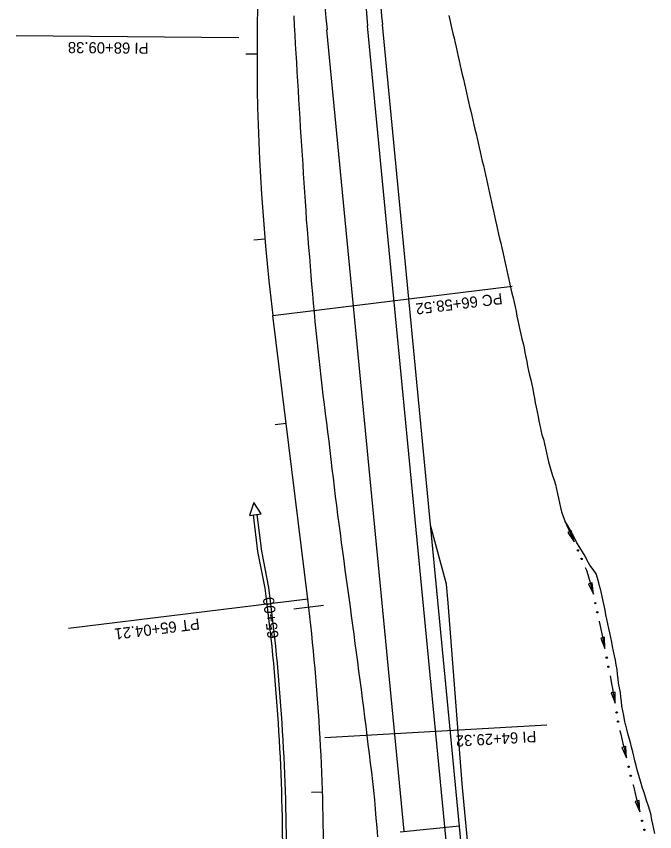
# Model space of a CAD drawing. Extents: x 1304554 to 1314558, y 2088110 to 2090513.
# Drawn here: x 1313834.3 to 1314178.7, y 2089497.1 to 2089937.1 of the extents above; entities that cross this region are included whole.
import ezdxf

# ---------------------------------------------------------------- set-up
doc = ezdxf.new("R2010")
doc.units = 0
for name, color, linetype in [('MOT_Barrier Wall Stage 3', 7, 'Continuous'), ('MOT_TIAB_Stage 3', 7, 'Continuous'), ('R_Horz Alg', 7, 'Continuous'), ('R_Horz Alg Annot', 7, 'Continuous'), ('R_Horz Alg Stationing', 7, 'Continuous'), ('R_Proposed Const Limits', 7, 'Continuous'), ('R_Proposed Road', 7, 'Continuous'), ('R_Shld_GR', 7, 'Continuous'), ('R_Shoulder', 7, 'Continuous'), ('R_Special Ditch', 7, 'Continuous')]:
    doc.layers.add(name, color=color, linetype=linetype)

msp = doc.modelspace()

# ---------------------------------------------------------------- linework, layer by layer
at = {"layer": 'MOT_Barrier Wall Stage 3'}
for p, q in [((1313962.26, 2089668.05), (1313964.24, 2089668.3)), ((1313964.69, 2089648.2), (1313962.26, 2089668.05)), ((1313966.68, 2089648.45), (1313964.24, 2089668.3)), ((1313968.62, 2089628.54), (1313964.69, 2089648.2)), ((1313970.6, 2089628.78), (1313966.68, 2089648.45)), ((1313969.69, 2089619.81), (1313968.62, 2089628.54)), ((1313971.68, 2089620.05), (1313970.6, 2089628.78))]:
    msp.add_line(p, q, dxfattribs=at)
for radius in [1123.92, 1125.92]:
    msp.add_arc((1312854.15, 2089482.84), radius, 359.5, 7, dxfattribs=at)
at = {"layer": 'MOT_TIAB_Stage 3'}
msp.add_lwpolyline([(1313962.43, 2089674.8), (1313960.13, 2089667.79), (1313966.36, 2089668.56)], close=True, dxfattribs=at)
at = {"layer": 'R_Horz Alg'}
msp.add_line((1313991.53, 2089622.49), (1313972.72, 2089775.65), dxfattribs=at)
msp.add_line((1313991.53, 2089622.49), (1313972.72, 2089775.65), dxfattribs=at)
for centre, start, end in [((1315110.09, 2089915.3), 172, 187), ((1312854.15, 2089482.84), 359.5, 7), ((1312854.15, 2089482.84), 359.5, 7)]:
    msp.add_arc(centre, 1145.92, start, end, dxfattribs=at)
at = {"layer": 'R_Horz Alg Annot'}
for points in [[(1313954.34, 2089925.39), (1313834.34, 2089926.44)], [(1313972.72, 2089775.65), (1314101.75, 2089791.49)], [(1313991.53, 2089622.49), (1313862.5, 2089606.65)], [(1314000.68, 2089547.94), (1314120.49, 2089554.75)]]:
    msp.add_lwpolyline(points, dxfattribs=at)
at = {"layer": 'R_Horz Alg Stationing'}
for points in [[(1313958.18, 2089916.79), (1313964.18, 2089916.78)], [(1313962.43, 2089816.39), (1313968.41, 2089816.91)], [(1313973.9, 2089716.84), (1313979.85, 2089717.57)], [(1313984.09, 2089617.37), (1313999.98, 2089619.26)], [(1313993.51, 2089518.44), (1313999.51, 2089518.62)]]:
    msp.add_lwpolyline(points, dxfattribs=at)
at = {"layer": 'R_Proposed Const Limits'}
for points in [[(1314029.32, 2089494.34), (1314028.9, 2089499.33), (1314028.49, 2089504.31), (1314028.08, 2089509.29), (1314027.64, 2089514.28), (1314027.18, 2089519.25), (1314026.65, 2089524.23), (1314026.02, 2089529.19), (1314025.4, 2089534.15), (1314024.79, 2089539.12), (1314024.17, 2089544.08), (1314023.57, 2089549.04), (1314022.97, 2089554.01), (1314022.37, 2089558.98), (1314021.76, 2089563.94), (1314021.13, 2089568.9), (1314020.46, 2089573.86), (1314019.79, 2089578.82), (1314019.13, 2089583.78), (1314018.47, 2089588.74), (1314017.81, 2089593.7), (1314017.16, 2089598.66), (1314016.51, 2089603.62), (1314015.85, 2089608.58), (1314015.17, 2089613.54), (1314014.5, 2089618.5), (1314013.83, 2089623.45), (1314013.16, 2089628.41), (1314012.48, 2089633.37), (1314011.79, 2089638.33), (1314011.11, 2089643.28), (1314010.44, 2089648.24), (1314009.78, 2089653.2), (1314009.12, 2089658.16), (1314008.48, 2089663.12), (1314007.84, 2089668.09), (1314007.2, 2089673.05), (1314006.57, 2089678.01), (1314005.94, 2089682.97), (1314005.33, 2089687.94), (1314004.74, 2089692.9), (1314004.18, 2089697.87), (1314003.62, 2089702.84), (1314003.02, 2089707.81), (1314002.42, 2089712.77), (1314001.8, 2089717.73), (1314001.15, 2089722.7), (1314000.5, 2089727.66), (1313999.86, 2089732.62), (1313999.26, 2089737.58), (1313998.73, 2089742.55), (1313998.2, 2089747.53), (1313997.67, 2089752.5), (1313997.14, 2089757.47), (1313996.62, 2089762.44), (1313996.11, 2089767.42), (1313995.6, 2089772.39), (1313995.08, 2089777.37), (1313994.61, 2089782.34), (1313994.2, 2089787.33), (1313993.79, 2089792.31), (1313993.38, 2089797.29), (1313992.97, 2089802.28), (1313992.57, 2089807.26), (1313992.16, 2089812.25), (1313991.75, 2089817.23), (1313991.33, 2089822.21), (1313990.94, 2089827.2), (1313990.62, 2089832.19), (1313990.29, 2089837.18), (1313989.97, 2089842.17), (1313989.64, 2089847.17), (1313989.3, 2089852.16), (1313988.97, 2089857.15), (1313988.65, 2089862.14), (1313988.3, 2089867.13), (1313987.94, 2089872.12), (1313987.65, 2089877.11), (1313987.38, 2089882.11), (1313987.1, 2089887.11), (1313986.79, 2089892.1), (1313986.49, 2089897.09), (1313986.2, 2089902.09), (1313985.9, 2089907.08), (1313985.58, 2089912.07), (1313985.25, 2089917.07), (1313984.93, 2089922.06), (1313984.67, 2089927.06), (1313984.41, 2089932.13), (1313984.15, 2089937.22)], [(1314067.61, 2089937.5), (1314068.16, 2089935.1), (1314068.72, 2089932.64), (1314069.28, 2089930.18), (1314069.84, 2089927.72), (1314070.41, 2089925.27), (1314070.97, 2089922.81), (1314071.51, 2089920.35), (1314072.05, 2089917.89), (1314072.61, 2089915.43), (1314073.18, 2089912.98), (1314073.75, 2089910.52), (1314074.32, 2089908.06), (1314074.89, 2089905.61), (1314075.47, 2089903.15), (1314076.03, 2089900.69), (1314076.58, 2089898.23), (1314077.13, 2089895.78), (1314077.7, 2089893.32), (1314078.27, 2089890.86), (1314078.85, 2089888.41), (1314079.43, 2089885.95), (1314080.02, 2089883.49), (1314080.59, 2089881.04), (1314081.16, 2089878.58), (1314081.73, 2089876.12), (1314082.29, 2089873.67), (1314082.86, 2089871.21), (1314083.42, 2089868.75), (1314083.98, 2089866.3), (1314084.54, 2089863.84), (1314085.1, 2089861.38), (1314085.67, 2089858.92), (1314086.24, 2089856.47), (1314086.8, 2089854.01), (1314087.35, 2089851.55), (1314087.9, 2089849.09), (1314088.45, 2089846.63), (1314088.99, 2089844.17), (1314089.53, 2089841.71), (1314090.07, 2089839.26), (1314090.63, 2089836.8), (1314091.19, 2089834.34), (1314091.74, 2089831.88), (1314092.3, 2089829.42), (1314092.85, 2089826.96), (1314093.39, 2089824.5), (1314093.93, 2089822.05), (1314094.47, 2089819.59), (1314095.03, 2089817.13), (1314095.59, 2089814.67), (1314096.15, 2089812.21), (1314096.71, 2089809.76), (1314097.27, 2089807.3), (1314097.83, 2089804.84), (1314098.39, 2089802.38), (1314098.95, 2089799.92), (1314099.5, 2089797.47), (1314100.04, 2089795.01), (1314100.58, 2089792.55), (1314101.13, 2089790.09), (1314101.69, 2089787.63), (1314102.25, 2089785.17), (1314102.26, 2089785.11), (1314102.81, 2089782.72), (1314103.37, 2089780.26), (1314103.89, 2089777.8), (1314104.37, 2089775.33), (1314104.85, 2089772.87), (1314105.38, 2089770.41), (1314105.95, 2089767.95), (1314106.52, 2089765.49), (1314107.08, 2089763.03), (1314107.65, 2089760.58), (1314108.21, 2089758.12), (1314108.7, 2089755.66), (1314109.16, 2089753.19), (1314109.63, 2089750.72), (1314110.13, 2089748.26), (1314110.67, 2089745.8), (1314111.22, 2089743.34), (1314111.77, 2089740.88), (1314112.31, 2089738.42), (1314112.85, 2089735.96), (1314113.3, 2089733.49), (1314113.75, 2089731.03), (1314114.19, 2089728.56), (1314114.67, 2089726.09), (1314115.2, 2089723.63), (1314115.72, 2089721.17), (1314116.25, 2089718.71), (1314116.77, 2089716.25), (1314117.08, 2089714.78), (1314117.27, 2089713.78), (1314117.7, 2089711.31), (1314118.65, 2089708.94), (1314118.66, 2089708.89), (1314119.17, 2089706.43), (1314119.7, 2089703.97), (1314120.29, 2089701.52), (1314120.87, 2089699.06), (1314121.46, 2089696.61), (1314122.04, 2089694.15), (1314122.74, 2089691.71), (1314123.54, 2089689.27), (1314124.35, 2089686.84), (1314125.08, 2089684.4), (1314125.62, 2089681.94), (1314126.16, 2089679.48), (1314126.7, 2089677.02), (1314127.26, 2089674.56), (1314127.86, 2089672.11), (1314128.46, 2089669.65), (1314129.34, 2089667.23)], [(1314178.65, 2089496.17), (1314178.16, 2089498.63), (1314177.67, 2089501.09), (1314177.17, 2089503.56), (1314176.76, 2089505.59), (1314176.68, 2089506.02), (1314176.04, 2089508.47), (1314175.27, 2089510.91), (1314174.49, 2089513.35), (1314173.72, 2089515.78), (1314172.94, 2089518.22), (1314172.16, 2089520.66), (1314171.39, 2089523.09), (1314170.64, 2089525.53), (1314169.89, 2089527.97), (1314169.19, 2089530.42), (1314168.59, 2089532.87), (1314167.99, 2089535.32), (1314167.39, 2089537.78), (1314166.79, 2089540.23), (1314166.18, 2089542.68), (1314165.58, 2089545.14), (1314164.91, 2089547.58), (1314164.24, 2089550.03), (1314163.56, 2089552.48), (1314163.01, 2089554.49), (1314162.92, 2089554.93), (1314162.44, 2089557.39), (1314161.94, 2089559.86), (1314161.44, 2089562.32), (1314160.96, 2089564.79), (1314160.7, 2089567.27), (1314160.43, 2089569.76), (1314160.16, 2089572.24), (1314159.68, 2089574.71), (1314159.2, 2089577.17), (1314158.89, 2089579.66), (1314158.61, 2089582.14), (1314158.33, 2089584.63), (1314157.95, 2089587.1), (1314157.47, 2089589.57), (1314156.99, 2089592.03), (1314156.5, 2089594.49), (1314155.98, 2089596.96), (1314155.47, 2089599.42), (1314154.97, 2089601.88), (1314154.46, 2089604.35), (1314153.96, 2089606.81), (1314153.43, 2089609.27), (1314152.9, 2089611.73), (1314152.38, 2089614.19), (1314151.86, 2089616.65), (1314151.33, 2089619.11), (1314150.8, 2089621.57), (1314150.25, 2089624.03), (1314149.72, 2089626.49), (1314149.35, 2089628.18), (1314149.27, 2089628.52), (1314149.15, 2089628.95), (1314148.48, 2089631.4), (1314147.8, 2089633.84), (1314147.03, 2089636.28), (1314145.49, 2089638.64), (1314143.71, 2089640.98), (1314142.26, 2089643.36), (1314141.1, 2089645.76), (1314139.74, 2089648.14), (1314138.22, 2089650.5), (1314136.75, 2089652.87), (1314135.56, 2089655.27), (1314134.37, 2089657.67), (1314133.03, 2089660.05), (1314131.6, 2089662.42), (1314130.27, 2089664.81)]]:
    msp.add_lwpolyline(points, dxfattribs=at)
at = {"layer": 'R_Proposed Road'}
for p, q in [((1314067.51, 2089477.98), (1314023.81, 2089931.84)), ((1314043.55, 2089497.3), (1314001.91, 2089929.73)), ((1314041.43, 2089497.1), (1314073.41, 2089500.18))]:
    msp.add_line(p, q, dxfattribs=at)
for radius, start in [(1420.39, 179.5), (1442.39, 181.3402)]:
    msp.add_arc((1315437.67, 2090067.97), radius, start, 185.5, dxfattribs=at)
at = {"layer": 'R_Shld_GR'}
for p, q in [((1314067.27, 2089620.62), (1314066.31, 2089630.58)), ((1314074.94, 2089520.83), (1314067.27, 2089620.62)), ((1314078.96, 2089479.08), (1314074.93, 2089520.9))]:
    msp.add_line(p, q, dxfattribs=at)
msp.add_lwpolyline([(1314066.31, 2089630.58), (1314057.79, 2089662.47)], dxfattribs=at)
at = {"layer": 'R_Shoulder'}
msp.add_line((1314075.48, 2089478.75), (1314031.77, 2089932.6), dxfattribs=at)
msp.add_arc((1315437.67, 2090067.97), 1412.39, 179.5, 185.5, dxfattribs=at)
at = {"layer": 'R_Special Ditch'}
for p, q in [((1314133.79, 2089659.35), (1314131.84, 2089658.5)), ((1314135.2, 2089653.42), (1314133.79, 2089659.35)), ((1314131.84, 2089658.5), (1314135.2, 2089653.42)), ((1314145.01, 2089631.39), (1314142.98, 2089630.79)), ((1314142.98, 2089630.79), (1314145.69, 2089625.33)), ((1314145.69, 2089625.33), (1314145.01, 2089631.39)), ((1314151.6, 2089601.99), (1314149.52, 2089601.57)), ((1314149.52, 2089601.57), (1314151.75, 2089595.9)), ((1314151.75, 2089595.9), (1314151.6, 2089601.99)), ((1314157.28, 2089572.47), (1314155.2, 2089572.11)), ((1314155.2, 2089572.11), (1314157.27, 2089566.38)), ((1314157.27, 2089566.38), (1314157.28, 2089572.47)), ((1314163.03, 2089543.07), (1314160.98, 2089542.58)), ((1314160.98, 2089542.58), (1314163.39, 2089536.99)), ((1314163.39, 2089536.99), (1314163.03, 2089543.07)), ((1314170.2, 2089513.91), (1314168.14, 2089513.4)), ((1314170.63, 2089507.84), (1314170.2, 2089513.91)), ((1314168.14, 2089513.4), (1314170.63, 2089507.84))]:
    msp.add_line(p, q, dxfattribs=at)
for points in [[(1314129.34, 2089667.23), (1314130.27, 2089664.81), (1314131.32, 2089662.39), (1314132.36, 2089659.98), (1314133.4, 2089657.57), (1314134.45, 2089655.16), (1314135.2, 2089653.42)], [(1314141.2, 2089639.67), (1314141.21, 2089639.64)], [(1314141.21, 2089639.64), (1314141.8, 2089638.29), (1314142.58, 2089635.85), (1314143.31, 2089633.41), (1314144.03, 2089630.97), (1314144.75, 2089628.53), (1314144.88, 2089628.1), (1314144.96, 2089627.76), (1314145.33, 2089626.07), (1314145.51, 2089625.28)], [(1314148.7, 2089610.63), (1314148.71, 2089610.59)], [(1314148.71, 2089610.59), (1314149.08, 2089608.85), (1314149.6, 2089606.39), (1314150.11, 2089603.93), (1314150.62, 2089601.46), (1314151.12, 2089599), (1314151.62, 2089596.54), (1314151.75, 2089595.9)], [(1314154.6, 2089581.18), (1314154.61, 2089581.14)], [(1314154.61, 2089581.14), (1314154.96, 2089579.28), (1314155.41, 2089576.81), (1314155.86, 2089574.34), (1314156.31, 2089571.87), (1314156.74, 2089569.4), (1314157.17, 2089566.93), (1314157.27, 2089566.38)], [(1314159.9, 2089551.61), (1314159.91, 2089551.58)], [(1314159.91, 2089551.58), (1314160.37, 2089549.66), (1314160.96, 2089547.2), (1314161.55, 2089544.75), (1314162.13, 2089542.29), (1314162.71, 2089539.84), (1314163.29, 2089537.38), (1314163.39, 2089536.99)], [(1314166.95, 2089522.42), (1314166.96, 2089522.38)], [(1314166.96, 2089522.38), (1314167.51, 2089520.21), (1314168.13, 2089517.76), (1314168.75, 2089515.3), (1314169.37, 2089512.85), (1314169.99, 2089510.4), (1314170.6, 2089507.95), (1314170.63, 2089507.84)]]:
    msp.add_lwpolyline(points, dxfattribs=at)
for centre in [(1314137.23, 2089648.84), (1314139.23, 2089644.25), (1314146.63, 2089620.4), (1314147.69, 2089615.51), (1314152.76, 2089591), (1314153.71, 2089586.08), (1314158.14, 2089561.45), (1314158.95, 2089556.5), (1314164.57, 2089532.12), (1314165.76, 2089527.25), (1314171.88, 2089502.99), (1314173.09, 2089498.12)]:
    msp.add_circle(centre, 0.375, dxfattribs=at)

# ---------------------------------------------------------------- texts
at = {"layer": 'R_Horz Alg Annot'}
for s, rotation, p in [('PI 68+09.38', 179.5, (1313905.65, 2089922.81)), ('PC 66+58.52', 187, (1314096.16, 2089787.78)), ('PT 65+04.21', 187, (1313932.83, 2089612.26)), ('PI 64+29.32', 183.25, (1314114.67, 2089551.41))]:
    msp.add_text(s, height=6, rotation=rotation, dxfattribs=at).set_placement(p)
at = {"layer": 'R_Horz Alg Stationing'}
msp.add_text('65+00', height=6, rotation=96.7896, dxfattribs=at).set_placement((1313975.89, 2089601.64))

doc.saveas('drawing.dxf')
